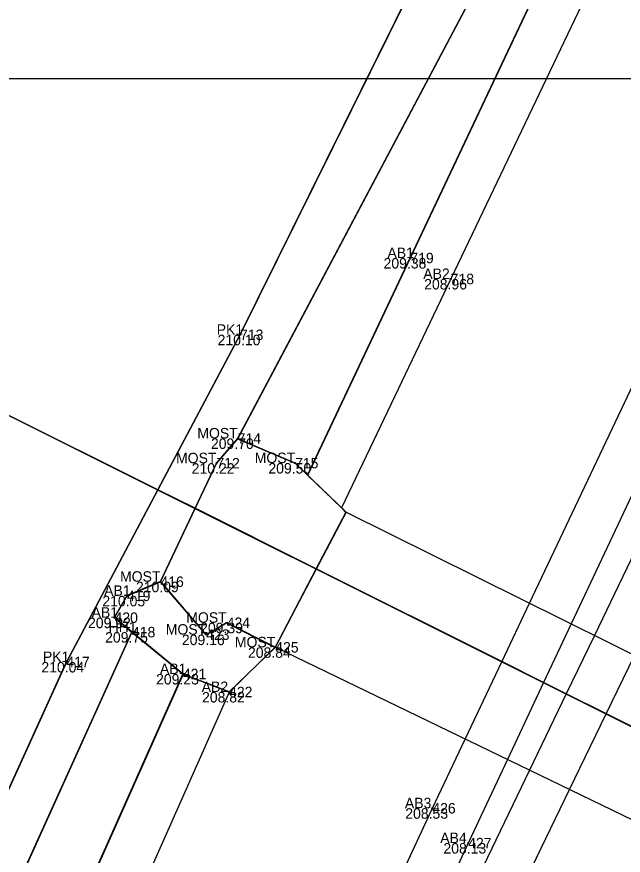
# Model space of a CAD drawing. Extents: x -263091 to -262565, y -1238731 to -1237092.
# Drawn here: x -262798.24 to -262786.65, y -1237679.73 to -1237663.71 of the extents above; entities that cross this region are included whole.
import ezdxf

# ---------------------------------------------------------------- set-up
doc = ezdxf.new("R2010")
doc.units = 0
for name, color, linetype in [('01_Hrana_betónu', 7, 'Continuous'), ('02_Oplotenie', 7, 'Continuous'), ('04_Most', 7, 'Continuous'), ('05_Hrana_terénu', 7, 'Continuous'), ('07_Iné', 7, 'Continuous'), ('10', 7, 'Continuous'), ('Groma (21)', 7, 'Continuous'), ('Groma (22)', 7, 'Continuous'), ('Groma (23)', 7, 'Continuous'), ('Groma (24)', 7, 'Continuous'), ('U004_Betónové_panely', 7, 'Continuous'), ('U004_Betóny_prídavné', 7, 'Continuous'), ('U004_Ostatné_plochy', 7, 'Continuous'), ('U004_Zeleň_mimo', 7, 'Continuous'), ('U004_Zeleň_vnútro', 7, 'Continuous'), ('U004_Zeleň_zatrávňovač', 7, 'Continuous'), ('U005_Betónové_panely', 7, 'Continuous'), ('U005_Ostatné_plochy', 7, 'Continuous'), ('U005_Zeleň_mimo', 7, 'Continuous'), ('U005_Zeleň_vnútro', 7, 'Continuous'), ('U005_Zeleň_zatrávňovač', 7, 'Continuous'), ('Vrstva 51', 7, 'Continuous')]:
    doc.layers.add(name, color=color, linetype=linetype)

msp = doc.modelspace()

# ---------------------------------------------------------------- linework, layer by layer
at = {"layer": '01_Hrana_betónu'}
for p, q in [((-262791.945, -1237673.175), (-262792.515, -1237674.262)), ((-262792.515, -1237674.262), (-262793.299, -1237675.758))]:
    msp.add_line(p, q, dxfattribs=at)
for points in [[(-262738.855, -1237311.192), (-262738.946, -1237318.051), (-262738.849, -1237332.413), (-262738.867, -1237356.312), (-262738.748, -1237377.69), (-262738.758, -1237401.69), (-262738.753, -1237425.185), (-262738.668, -1237459.096), (-262739.01, -1237478.875), (-262739.257, -1237501.361), (-262739.436, -1237524.506), (-262739.635, -1237547.624), (-262739.863, -1237556.5), (-262740.784, -1237566.075), (-262742.123, -1237574.161), (-262744.555, -1237583.315), (-262747.793, -1237592.067), (-262752.033, -1237601.877), (-262761.381, -1237621.164), (-262771.059, -1237641.465), (-262778.806, -1237657.918), (-262784.861, -1237670.667), (-262787.201, -1237675.529)], [(-262739.343, -1237311.485), (-262739.423, -1237318.909), (-262739.337, -1237332.42), (-262739.334, -1237355.849), (-262739.135, -1237377.701), (-262739.178, -1237401.786), (-262739.257, -1237424.031), (-262739.458, -1237458.924), (-262739.421, -1237479.296), (-262739.718, -1237500.116), (-262739.917, -1237524.824), (-262740.163, -1237546.913), (-262740.342, -1237556.649), (-262741.144, -1237564.78), (-262742.646, -1237573.838), (-262744.715, -1237582.455), (-262748.007, -1237591.229), (-262752.529, -1237601.669), (-262761.584, -1237620.386), (-262771.44, -1237641.076), (-262779.114, -1237657.574), (-262785.318, -1237670.364), (-262787.643, -1237675.31)], [(-262788.441, -1237674.914), (-262786.102, -1237669.974), (-262779.96, -1237657.146), (-262772.255, -1237640.671), (-262762.405, -1237620.082), (-262753.353, -1237601.237), (-262748.855, -1237590.92), (-262745.54, -1237582.117), (-262743.431, -1237573.688), (-262742.016, -1237564.7), (-262741.168, -1237556.501), (-262740.979, -1237546.892), (-262740.851, -1237524.752), (-262740.671, -1237500.08), (-262740.394, -1237479.483), (-262740.216, -1237458.955), (-262740.117, -1237423.647), (-262740.094, -1237401.75), (-262740.13, -1237377.708), (-262740.243, -1237355.929), (-262740.317, -1237332.345), (-262740.44, -1237318.894), (-262740.323, -1237312.076)], [(-262744.671, -1237314.693), (-262744.322, -1237332.28), (-262744.032, -1237356.103), (-262743.621, -1237377.876), (-262743.427, -1237401.834), (-262743.334, -1237423.507), (-262743.665, -1237455.163), (-262743.89, -1237458.66), (-262743.816, -1237479.543), (-262744.125, -1237500.374), (-262744.256, -1237524.891), (-262744.407, -1237545.149), (-262744.747, -1237556.085), (-262745.544, -1237564.593), (-262746.648, -1237572.023), (-262748.879, -1237581.03), (-262752.099, -1237589.665), (-262756.673, -1237599.828), (-262765.314, -1237617.226), (-262775.804, -1237639.013), (-262783.576, -1237655.372), (-262792.033, -1237673.09)], [(-262792.676, -1237672.47), (-262784.421, -1237654.971), (-262776.677, -1237638.569), (-262766.087, -1237616.912), (-262757.487, -1237599.378), (-262752.942, -1237589.379), (-262749.712, -1237580.796), (-262747.504, -1237571.715), (-262746.486, -1237564.414), (-262745.673, -1237555.98), (-262745.336, -1237545.322), (-262745.216, -1237524.737), (-262745.016, -1237500.506), (-262744.745, -1237479.418), (-262744.873, -1237458.479), (-262744.515, -1237455.206), (-262744.284, -1237423.517), (-262744.408, -1237401.828), (-262744.521, -1237377.717), (-262744.916, -1237356.111), (-262745.155, -1237332.402), (-262745.296, -1237327.881), (-262745.213, -1237324.651), (-262745.472, -1237315.175)], [(-262788.971, -1237676.033), (-262788.441, -1237674.914)], [(-262787.643, -1237675.31), (-262788.171, -1237676.433)], [(-262787.201, -1237675.529), (-262787.74, -1237676.649)], [(-262786.974, -1237677.031), (-262786.432, -1237675.911)], [(-262789.671, -1237677.512), (-262788.971, -1237676.033)], [(-262833.49, -1237932.513), (-262832.358, -1237924.572), (-262831.993, -1237918.626), (-262831.904, -1237915.074), (-262831.439, -1237906.309), (-262830.324, -1237884.482), (-262828.859, -1237869.656), (-262826.973, -1237856.487), (-262824.752, -1237845.872), (-262820.768, -1237827.409), (-262815.971, -1237805.011), (-262811.874, -1237785.528), (-262810.073, -1237767.205), (-262809.465, -1237744.209), (-262809.348, -1237719.32), (-262807.762, -1237709.127), (-262805.583, -1237701.261), (-262801.096, -1237689.829), (-262795.064, -1237676.268)], [(-262788.171, -1237676.433), (-262788.862, -1237677.903)], [(-262794.181, -1237676.612), (-262800.21, -1237690.201), (-262804.735, -1237701.618), (-262806.814, -1237709.415), (-262808.46, -1237719.391), (-262808.589, -1237744.23), (-262809.169, -1237767.262), (-262810.977, -1237785.858), (-262815.119, -1237805.286), (-262819.878, -1237827.449), (-262823.898, -1237846.237), (-262826.14, -1237856.747), (-262827.996, -1237869.725), (-262829.453, -1237884.611), (-262830.572, -1237906.318), (-262830.909, -1237915.064), (-262831.044, -1237918.638), (-262831.379, -1237924.623), (-262832.499, -1237932.636), (-262832.416, -1237932.646)], [(-262787.74, -1237676.649), (-262788.441, -1237678.106)], [(-262787.674, -1237678.477), (-262786.974, -1237677.031)], [(-262828.366, -1237932.946), (-262828.106, -1237929.217), (-262827.649, -1237919.578), (-262827.369, -1237915.073), (-262826.968, -1237906.664), (-262825.835, -1237884.909), (-262824.318, -1237870.338), (-262822.252, -1237856.88), (-262820.394, -1237847.242), (-262816.344, -1237828.005), (-262811.527, -1237806.128), (-262807.485, -1237786.652), (-262805.817, -1237767.526), (-262804.904, -1237743.876), (-262804.544, -1237721.54), (-262802.773, -1237710.111), (-262800.948, -1237703.699), (-262796.578, -1237692.416), (-262790.297, -1237678.834), (-262789.671, -1237677.512)], [(-262788.862, -1237677.903), (-262789.612, -1237679.5), (-262795.758, -1237692.783), (-262800.102, -1237704.105), (-262801.904, -1237710.319), (-262803.638, -1237721.631), (-262804.041, -1237743.855), (-262804.886, -1237767.666), (-262806.567, -1237786.84), (-262810.653, -1237806.707), (-262815.575, -1237828.361), (-262819.614, -1237847.41), (-262821.404, -1237856.927), (-262823.638, -1237870.532), (-262825.083, -1237884.947), (-262826.299, -1237906.725), (-262827.242, -1237929.453), (-262827.527, -1237933.008)], [(-262788.441, -1237678.106), (-262789.499, -1237680.304), (-262796.488, -1237695.789), (-262799.561, -1237704.378), (-262801.599, -1237711.648), (-262803.17, -1237722.277), (-262803.523, -1237744.912), (-262804.331, -1237767.555), (-262806.033, -1237786.907), (-262810.428, -1237808.027), (-262815.321, -1237829.941), (-262818.5, -1237845.545), (-262820.865, -1237857.635), (-262822.962, -1237871.266), (-262824.386, -1237885.795), (-262825.49, -1237906.658), (-262826.835, -1237930.337), (-262826.931, -1237933.053)], [(-262825.987, -1237933.123), (-262825.899, -1237930.36), (-262825.137, -1237919.703), (-262824.89, -1237915.193), (-262824.65, -1237906.715), (-262823.596, -1237885.855), (-262822.137, -1237871.403), (-262820.061, -1237857.781), (-262817.692, -1237845.812), (-262814.459, -1237830.149), (-262809.645, -1237808.205), (-262805.191, -1237787.117), (-262803.484, -1237767.641), (-262802.568, -1237744.998), (-262802.266, -1237722.317), (-262800.862, -1237712.121), (-262798.805, -1237704.616), (-262795.791, -1237696.17), (-262788.393, -1237679.964), (-262787.674, -1237678.477)]]:
    msp.add_lwpolyline(points, dxfattribs=at)
at = {"layer": '02_Oplotenie'}
for points in [[(-262793.971, -1237669.784), (-262786.051, -1237653.784), (-262778.339, -1237638.096), (-262767.839, -1237615.998), (-262759.49, -1237598.413), (-262754.828, -1237588.44), (-262751.768, -1237579.927), (-262749.971, -1237571.226), (-262749.021, -1237564.318), (-262748.215, -1237555.413), (-262747.787, -1237545.2), (-262747.818, -1237524.565), (-262747.681, -1237500.551), (-262747.391, -1237479.445), (-262747.231, -1237460.146), (-262746.875, -1237423.458), (-262747.304, -1237401.954), (-262748.156, -1237377.36), (-262748.89, -1237356.224), (-262749.247, -1237329.045)], [(-262834.343, -1237921.203), (-262834.024, -1237915.302), (-262833.812, -1237906.279), (-262832.732, -1237884.616), (-262831.151, -1237869.343), (-262829.251, -1237856.325), (-262826.951, -1237845.31), (-262823.094, -1237827.731), (-262817.951, -1237804.339), (-262814.023, -1237784.135), (-262812.336, -1237767.05), (-262811.754, -1237744.594), (-262811.555, -1237719.093), (-262809.863, -1237708.888), (-262807.835, -1237700.632), (-262803.244, -1237689.13), (-262797.291, -1237676.038)]]:
    msp.add_lwpolyline(points, dxfattribs=at)
at = {"layer": '04_Most'}
for points in [[(-262794.832, -1237673.105), (-262794.423, -1237672.239), (-262794.016, -1237671.765), (-262792.919, -1237672.236), (-262791.945, -1237673.175), (-262782.754, -1237677.736), (-262781.704, -1237678.283), (-262781.563, -1237678.037), (-262780.7, -1237678.426), (-262780.481, -1237679.127), (-262780.925, -1237680.054)], [(-262780.925, -1237680.054), (-262781.499, -1237681.254), (-262782.189, -1237681.436), (-262783, -1237681.174), (-262782.961, -1237680.851), (-262783.935, -1237680.285), (-262793.299, -1237675.758), (-262794.227, -1237675.288), (-262794.619, -1237675.515), (-262795.493, -1237674.504), (-262794.832, -1237673.105)]]:
    msp.add_lwpolyline(points, dxfattribs=at)
at = {"layer": '05_Hrana_terénu'}
for points in [[(-262746.684, -1237500.449), (-262746.883, -1237524.672), (-262746.96, -1237545.219), (-262747.259, -1237555.728), (-262748.105, -1237564.398), (-262749.066, -1237571.186), (-262750.795, -1237580.085), (-262754.134, -1237588.771), (-262758.577, -1237598.887), (-262767.121, -1237616.464), (-262785.488, -1237654.334), (-262789.051, -1237662.387), (-262794.016, -1237671.765)], [(-262796.037, -1237675.468), (-262802.307, -1237689.303), (-262806.908, -1237700.928), (-262808.861, -1237708.991), (-262810.491, -1237719.246), (-262810.648, -1237744.371), (-262811.212, -1237767.185), (-262812.78, -1237784.48), (-262817.048, -1237804.549), (-262821.958, -1237827.467), (-262825.893, -1237845.536), (-262828.436, -1237856.363), (-262830.087, -1237869.518), (-262831.495, -1237884.449), (-262832.703, -1237906.272), (-262832.889, -1237914.228), (-262832.974, -1237914.835)]]:
    msp.add_lwpolyline(points, dxfattribs=at)
at = {"layer": '07_Iné'}
msp.add_lwpolyline([(-262793.299, -1237675.758), (-262794.181, -1237676.612), (-262795.064, -1237676.268), (-262796.37, -1237675.191), (-262796.131, -1237674.774), (-262795.493, -1237674.504)], dxfattribs=at)
at = {"layer": '10'}
msp.add_lwpolyline([(-262813.033, -1237664.011), (-262780.925, -1237680.054), (-262777.93, -1237681.41), (-262750.961, -1237695.025)], dxfattribs=at)
at = {"layer": 'Groma (21)'}
for centre in [(-262790.717, -1237668.317), (-262789.946, -1237668.717), (-262793.971, -1237669.784), (-262794.016, -1237671.765), (-262794.423, -1237672.239), (-262792.919, -1237672.236), (-262795.493, -1237674.504), (-262796.131, -1237674.774), (-262796.37, -1237675.191), (-262794.227, -1237675.288), (-262796.037, -1237675.468), (-262794.619, -1237675.515), (-262793.299, -1237675.758), (-262797.291, -1237676.038), (-262795.064, -1237676.268), (-262794.181, -1237676.612), (-262790.297, -1237678.834), (-262789.612, -1237679.5)]:
    msp.add_circle(centre, 0.01, dxfattribs=at)
at = {"layer": 'U004_Betónové_panely'}
msp.add_lwpolyline([(-262809.47, -1237744.21), (-262809.35, -1237719.32), (-262807.76, -1237709.13), (-262805.58, -1237701.26), (-262801.1, -1237689.83), (-262795.06, -1237676.27), (-262794.18, -1237676.61), (-262793.3, -1237675.76), (-262792.52, -1237674.26), (-262788.97, -1237676.03), (-262788.17, -1237676.43), (-262787.74, -1237676.65), (-262786.97, -1237677.03), (-262783.28, -1237678.88), (-262783.94, -1237680.28), (-262783.8, -1237680.36), (-262791.07, -1237697.73), (-262794.16, -1237706.2), (-262796.11, -1237713.49), (-262797.35, -1237722.8)], dxfattribs=at)
msp.add_lwpolyline([(-262809.47, -1237744.21), (-262809.35, -1237719.32), (-262807.76, -1237709.13), (-262805.58, -1237701.26), (-262801.1, -1237689.83), (-262795.06, -1237676.27), (-262794.18, -1237676.61), (-262793.3, -1237675.76), (-262792.52, -1237674.26), (-262788.97, -1237676.03), (-262788.17, -1237676.43), (-262787.74, -1237676.65), (-262786.97, -1237677.03), (-262783.28, -1237678.88), (-262783.94, -1237680.28), (-262783.8, -1237680.36), (-262791.07, -1237697.73), (-262794.16, -1237706.2), (-262796.11, -1237713.49), (-262797.35, -1237722.8)], dxfattribs=at)
at = {"layer": 'U004_Betóny_prídavné'}
msp.add_lwpolyline([(-262796.37, -1237675.19), (-262796.13, -1237674.77), (-262795.49, -1237674.5), (-262794.62, -1237675.52), (-262794.23, -1237675.29), (-262793.3, -1237675.76), (-262794.18, -1237676.61), (-262795.06, -1237676.27)], close=True, dxfattribs=at)
msp.add_lwpolyline([(-262794.18, -1237676.61), (-262795.06, -1237676.27), (-262796.37, -1237675.19), (-262796.13, -1237674.77), (-262795.49, -1237674.5), (-262794.62, -1237675.52), (-262794.23, -1237675.29), (-262793.3, -1237675.76), (-262794.18, -1237676.61)], dxfattribs=at)
at = {"layer": 'U004_Ostatné_plochy'}
msp.add_lwpolyline([(-262792.52, -1237674.26), (-262793.3, -1237675.76), (-262794.23, -1237675.29), (-262794.62, -1237675.52), (-262795.49, -1237674.5), (-262794.83, -1237673.1)], close=True, dxfattribs=at)
msp.add_lwpolyline([(-262793.3, -1237675.76), (-262794.23, -1237675.29), (-262794.62, -1237675.52), (-262795.49, -1237674.5), (-262794.83, -1237673.1), (-262792.52, -1237674.26), (-262793.3, -1237675.76)], dxfattribs=at)
at = {"layer": 'U004_Zeleň_mimo'}
msp.add_lwpolyline([(-262829.89, -1237759.64), (-262821.36, -1237713.08), (-262832.88, -1237711.03), (-262837.42, -1237710.15), (-262826.67, -1237665.04), (-262821.31, -1237667.32), (-262810.29, -1237671.46), (-262808.34, -1237666.36), (-262795.54, -1237672.75), (-262797.29, -1237676.04), (-262803.24, -1237689.13), (-262807.84, -1237700.63), (-262809.86, -1237708.89), (-262811.56, -1237719.09), (-262811.75, -1237744.59)], dxfattribs=at)
at = {"layer": 'U004_Zeleň_vnútro'}
msp.add_lwpolyline([(-262811.75, -1237744.59), (-262811.56, -1237719.09), (-262809.86, -1237708.89), (-262807.84, -1237700.63), (-262803.24, -1237689.13), (-262797.29, -1237676.04), (-262795.54, -1237672.75), (-262794.83, -1237673.1), (-262795.49, -1237674.5), (-262796.13, -1237674.77), (-262796.37, -1237675.19), (-262796.04, -1237675.47), (-262802.31, -1237689.3), (-262806.91, -1237700.93), (-262808.86, -1237708.99), (-262810.49, -1237719.25), (-262810.65, -1237744.37)], dxfattribs=at)
msp.add_lwpolyline([(-262811.75, -1237744.59), (-262811.56, -1237719.09), (-262809.86, -1237708.89), (-262807.84, -1237700.63), (-262803.24, -1237689.13), (-262797.29, -1237676.04), (-262795.54, -1237672.75), (-262794.83, -1237673.1), (-262795.49, -1237674.5), (-262796.13, -1237674.77), (-262796.37, -1237675.19), (-262796.04, -1237675.47), (-262802.31, -1237689.3), (-262806.91, -1237700.93), (-262808.86, -1237708.99), (-262810.49, -1237719.25), (-262810.65, -1237744.37)], dxfattribs=at)
at = {"layer": 'U004_Zeleň_zatrávňovač'}
msp.add_lwpolyline([(-262810.65, -1237744.37), (-262810.49, -1237719.25), (-262808.86, -1237708.99), (-262806.91, -1237700.93), (-262802.31, -1237689.3), (-262796.04, -1237675.47), (-262795.06, -1237676.27), (-262801.1, -1237689.83), (-262805.58, -1237701.26), (-262807.76, -1237709.13), (-262809.35, -1237719.32), (-262809.47, -1237744.21)], dxfattribs=at)
msp.add_lwpolyline([(-262810.65, -1237744.37), (-262810.49, -1237719.25), (-262808.86, -1237708.99), (-262806.91, -1237700.93), (-262802.31, -1237689.3), (-262796.04, -1237675.47), (-262795.06, -1237676.27), (-262801.1, -1237689.83), (-262805.58, -1237701.26), (-262807.76, -1237709.13), (-262809.35, -1237719.32), (-262809.47, -1237744.21)], dxfattribs=at)
at = {"layer": 'U005_Betónové_panely'}
for points in [[(-262783.28, -1237678.88), (-262786.97, -1237677.03), (-262787.74, -1237676.65), (-262788.17, -1237676.43), (-262788.97, -1237676.03), (-262792.52, -1237674.26), (-262791.95, -1237673.18), (-262792.03, -1237673.09), (-262792.68, -1237672.47), (-262784.42, -1237654.97), (-262776.68, -1237638.57), (-262766.09, -1237616.91), (-262757.49, -1237599.38), (-262752.94, -1237589.38), (-262749.71, -1237580.8), (-262747.5, -1237571.72), (-262746.49, -1237564.41), (-262745.67, -1237555.98), (-262745.34, -1237545.32), (-262745.22, -1237524.74), (-262745.02, -1237500.51)], [(-262747.21, -1237604.2), (-262756.24, -1237623.63), (-262765.96, -1237644.11), (-262773.68, -1237660.32), (-262779.99, -1237673.1), (-262781.45, -1237675.8), (-262782.33, -1237677.96), (-262782.75, -1237677.74), (-262783.28, -1237678.88), (-262786.97, -1237677.03), (-262787.74, -1237676.65), (-262788.17, -1237676.43), (-262788.97, -1237676.03), (-262792.52, -1237674.26), (-262791.95, -1237673.18), (-262792.03, -1237673.09), (-262792.68, -1237672.47), (-262784.42, -1237654.97), (-262776.68, -1237638.57), (-262766.09, -1237616.91)]]:
    msp.add_lwpolyline(points, dxfattribs=at)
at = {"layer": 'U005_Ostatné_plochy'}
msp.add_lwpolyline([(-262792.52, -1237674.26), (-262794.83, -1237673.1), (-262794.42, -1237672.24), (-262794.02, -1237671.77), (-262792.92, -1237672.24), (-262792.68, -1237672.47), (-262792.03, -1237673.09), (-262791.95, -1237673.18)], close=True, dxfattribs=at)
msp.add_lwpolyline([(-262792.52, -1237674.26), (-262794.83, -1237673.1), (-262794.42, -1237672.24), (-262794.02, -1237671.77), (-262792.92, -1237672.24), (-262792.68, -1237672.47), (-262792.03, -1237673.09), (-262791.95, -1237673.18), (-262792.52, -1237674.26)], dxfattribs=at)
at = {"layer": 'U005_Zeleň_mimo'}
msp.add_lwpolyline([(-262747.68, -1237500.55), (-262747.82, -1237524.57), (-262747.79, -1237545.2), (-262748.22, -1237555.41), (-262749.02, -1237564.32), (-262749.97, -1237571.23), (-262751.77, -1237579.93), (-262754.83, -1237588.44), (-262759.49, -1237598.41), (-262767.84, -1237616), (-262778.34, -1237638.1), (-262786.05, -1237653.78), (-262793.97, -1237669.78), (-262795.54, -1237672.75), (-262808.34, -1237666.36), (-262793.39, -1237627.04), (-262791.78, -1237622.95), (-262787.11, -1237623.75), (-262784.13, -1237624.4), (-262781.33, -1237608.15), (-262778.14, -1237587.84), (-262773.94, -1237562.14), (-262768.34, -1237527.64), (-262757.02, -1237455.96)], dxfattribs=at)
at = {"layer": 'U005_Zeleň_vnútro'}
for points in [[(-262746.68, -1237500.45), (-262746.88, -1237524.67), (-262746.96, -1237545.22), (-262747.26, -1237555.73), (-262748.11, -1237564.4), (-262749.07, -1237571.19), (-262750.8, -1237580.09), (-262754.13, -1237588.77), (-262758.58, -1237598.89), (-262767.12, -1237616.46), (-262785.49, -1237654.33), (-262789.05, -1237662.39), (-262794.02, -1237671.77), (-262794.42, -1237672.24), (-262794.83, -1237673.1)], [(-262794.83, -1237673.1), (-262795.54, -1237672.75), (-262793.97, -1237669.78), (-262786.05, -1237653.78), (-262778.34, -1237638.1), (-262767.84, -1237616), (-262759.49, -1237598.41), (-262754.83, -1237588.44), (-262751.77, -1237579.93), (-262749.97, -1237571.23), (-262749.02, -1237564.32), (-262748.22, -1237555.41), (-262747.79, -1237545.2), (-262747.82, -1237524.57), (-262747.68, -1237500.55)], [(-262767.12, -1237616.46), (-262785.49, -1237654.33), (-262789.05, -1237662.39), (-262794.02, -1237671.77), (-262794.42, -1237672.24), (-262794.83, -1237673.1), (-262795.54, -1237672.75), (-262793.97, -1237669.78), (-262786.05, -1237653.78), (-262778.34, -1237638.1), (-262767.84, -1237616)]]:
    msp.add_lwpolyline(points, dxfattribs=at)
at = {"layer": 'U005_Zeleň_zatrávňovač'}
for points in [[(-262792.68, -1237672.47), (-262792.92, -1237672.24), (-262794.02, -1237671.77), (-262789.05, -1237662.39), (-262785.49, -1237654.33), (-262767.12, -1237616.46), (-262758.58, -1237598.89), (-262754.13, -1237588.77), (-262750.8, -1237580.09), (-262749.07, -1237571.19), (-262748.11, -1237564.4), (-262747.26, -1237555.73), (-262746.96, -1237545.22), (-262746.88, -1237524.67), (-262746.68, -1237500.45)], [(-262745.02, -1237500.51), (-262745.22, -1237524.74), (-262745.34, -1237545.32), (-262745.67, -1237555.98), (-262746.49, -1237564.41), (-262747.5, -1237571.72), (-262749.71, -1237580.8), (-262752.94, -1237589.38), (-262757.49, -1237599.38), (-262766.09, -1237616.91), (-262776.68, -1237638.57), (-262784.42, -1237654.97), (-262792.68, -1237672.47)], [(-262766.09, -1237616.91), (-262776.68, -1237638.57), (-262784.42, -1237654.97), (-262792.68, -1237672.47), (-262792.92, -1237672.24), (-262794.02, -1237671.77), (-262789.05, -1237662.39), (-262785.49, -1237654.33), (-262767.12, -1237616.46)]]:
    msp.add_lwpolyline(points, dxfattribs=at)
at = {"layer": 'Vrstva 51'}
msp.add_lwpolyline([(-262609.436, -1238258.884), (-263029.436, -1238258.884), (-263029.436, -1237664.884), (-262609.436, -1237664.884)], close=True, dxfattribs=at)

# ---------------------------------------------------------------- texts
at = {"layer": 'Groma (22)'}
for s, p in [('719', (-262790.717, -1237668.417)), ('718', (-262789.946, -1237668.817)), ('713', (-262793.971, -1237669.884)), ('714', (-262794.016, -1237671.865)), ('712', (-262794.423, -1237672.339)), ('715', (-262792.919, -1237672.336)), ('416', (-262795.493, -1237674.604)), ('419', (-262796.131, -1237674.874)), ('420', (-262796.37, -1237675.291)), ('424', (-262794.227, -1237675.388)), ('418', (-262796.037, -1237675.568)), ('423', (-262794.619, -1237675.615)), ('425', (-262793.299, -1237675.858)), ('417', (-262797.291, -1237676.138)), ('421', (-262795.064, -1237676.368)), ('422', (-262794.181, -1237676.712)), ('426', (-262790.297, -1237678.934)), ('427', (-262789.612, -1237679.6))]:
    msp.add_text(s, height=0.2, dxfattribs=at).set_placement(p)
at = {"layer": 'Groma (23)'}
for s, p in [('209.38', (-262791.229, -1237668.517)), ('208.96', (-262790.453, -1237668.917)), ('210.10', (-262794.4, -1237669.984)), ('209.70', (-262794.528, -1237671.965)), ('210.22', (-262794.896, -1237672.439)), ('209.50', (-262793.43, -1237672.436)), ('210.09', (-262795.961, -1237674.704)), ('210.05', (-262796.603, -1237674.974)), ('209.92', (-262796.877, -1237675.391)), ('209.39', (-262794.734, -1237675.488)), ('209.75', (-262796.55, -1237675.668)), ('209.16', (-262795.083, -1237675.715)), ('208.84', (-262793.82, -1237675.958)), ('210.04', (-262797.768, -1237676.238)), ('209.23', (-262795.576, -1237676.468)), ('208.82', (-262794.698, -1237676.812)), ('208.53', (-262790.814, -1237679.034)), ('208.13', (-262790.085, -1237679.7))]:
    msp.add_text(s, height=0.2, dxfattribs=at).set_placement(p)
at = {"layer": 'Groma (24)'}
for s, p in [('AB1', (-262791.155, -1237668.317)), ('AB2', (-262790.47, -1237668.717)), ('PK1', (-262794.418, -1237669.784)), ('MOST', (-262794.788, -1237671.765)), ('MOST', (-262795.195, -1237672.239)), ('MOST', (-262793.691, -1237672.236)), ('MOST', (-262796.265, -1237674.504)), ('AB1', (-262796.569, -1237674.774)), ('AB1', (-262796.808, -1237675.191)), ('MOST', (-262794.999, -1237675.288)), ('HH1', (-262796.484, -1237675.468)), ('MOST', (-262795.391, -1237675.515)), ('MOST', (-262794.071, -1237675.758)), ('PK1', (-262797.738, -1237676.038)), ('AB1', (-262795.502, -1237676.268)), ('AB2', (-262794.705, -1237676.612)), ('AB3', (-262790.821, -1237678.834)), ('AB4', (-262790.146, -1237679.5))]:
    msp.add_text(s, height=0.2, dxfattribs=at).set_placement(p)

doc.saveas('drawing.dxf')
